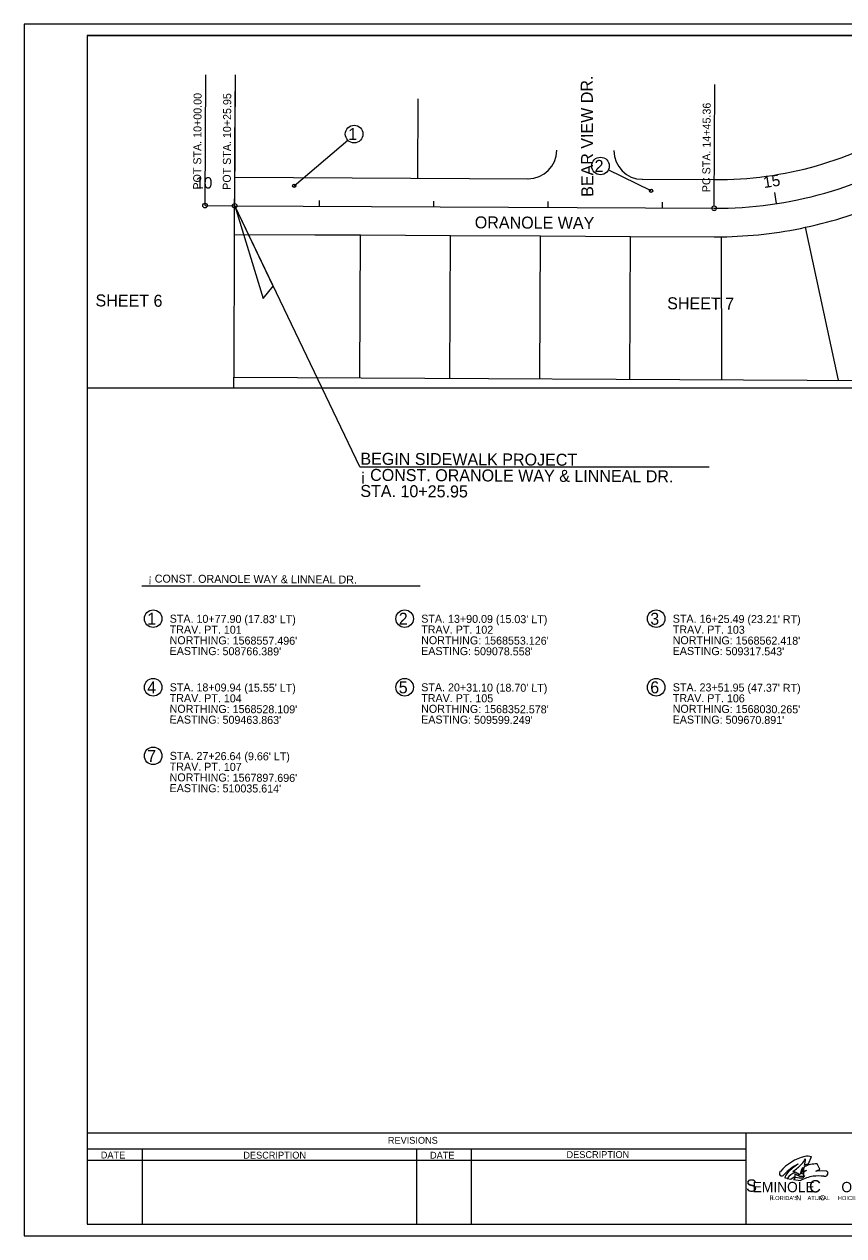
# Model space of a CAD drawing. Extents: x 508530 to 510180, y 1567639 to 1568699.
# Drawn here: x 508530 to 509247, y 1567639 to 1568699 of the extents above; entities that cross this region are included whole.
import ezdxf

# ---------------------------------------------------------------- set-up
doc = ezdxf.new("R2010")
doc.units = 0
for name, color, linetype in [('AdhocPoint_dp', 7, 'Continuous'), ('CLConst_dp', 7, 'Continuous'), ('CurveDataLabel_dp', 7, 'Continuous'), ('LeaderLine_dp', 7, 'Continuous'), ('Logo_dp', 7, 'Continuous'), ('NonPlottingEle_dp', 7, 'Continuous'), ('PlotBorder_dp', 7, 'Continuous'), ('RWLine_ep', 7, 'Continuous'), ('ScratchEle_dp', 7, 'Continuous'), ('SheetBorder_dp', 7, 'Continuous'), ('SheetLines_dp', 7, 'Continuous'), ('StationTicL_dp', 7, 'Continuous'), ('StationTicS_dp', 7, 'Continuous'), ('SubDivLine', 7, 'Continuous'), ('TextBLStation', 7, 'Continuous'), ('TextMisc', 7, 'Continuous')]:
    doc.layers.add(name, color=color, linetype=linetype)

msp = doc.modelspace()

# ---------------------------------------------------------------- linework, layer by layer
at = {"layer": 'AdhocPoint_dp'}
msp.add_line((508530.3, 1567638.8), (508530.3, 1567638.8), dxfattribs=at)
at = {"layer": 'CLConst_dp'}
for p, q in [((508688.4, 1568540.1), (508714.3, 1568539.9)), ((508714.3, 1568539.9), (509133.7, 1568537.8))]:
    msp.add_line(p, q, dxfattribs=at)
msp.add_arc((509135.5, 1568885.1), 347.3, 269.7131, 302.0065, dxfattribs=at)
at = {"layer": 'CurveDataLabel_dp'}
for p, q in [((508688.4, 1568542.1), (508689, 1568654.5)), ((508714.4, 1568541.9), (508714.9, 1568654.5)), ((509133.8, 1568539.8), (509134.3, 1568646.1))]:
    msp.add_line(p, q, dxfattribs=at)
for centre in [(508688.4, 1568540.1), (508714.3, 1568539.9), (509133.7, 1568537.8)]:
    msp.add_circle(centre, 2, dxfattribs=at)
at = {"layer": 'LeaderLine_dp'}
for p, q in [((508714.4, 1568539.9), (508739.3, 1568458.7)), ((508748.1, 1568469.6), (508714.4, 1568539.9)), ((508739.3, 1568458.7), (508748.1, 1568469.6))]:
    msp.add_line(p, q, dxfattribs=at)
at = {"layer": 'Logo_dp'}
for p, q in [((509216.3, 1567701.6), (509218.9, 1567708)), ((509226, 1567697.1), (509223.7, 1567701.7)), ((509197.5, 1567689), (509200.9, 1567688.4)), ((509200.9, 1567688.4), (509204.6, 1567690.8)), ((509203.2, 1567687.9), (509209.2, 1567687.1)), ((509204.6, 1567690.8), (509204.6, 1567692.3)), ((509206.3, 1567691.9), (509207.7, 1567692.8)), ((509212.7, 1567691.6), (509211.4, 1567689.6)), ((509231.6, 1567695.3), (509222.8, 1567695.5))]:
    msp.add_line(p, q, dxfattribs=at)
for points in [[(509212.9, 1567708.1), (509212.9, 1567708.1)], [(509198.1, 1567694.1), (509198.1, 1567694.1)]]:
    msp.add_lwpolyline(points, dxfattribs=at)
for centre, radius, start, end in [((509215.7, 1567696), 12.4, 75.3253, 102.9903), ((509221.9, 1567669.4), 39.7, 102.9903, 139.6059), ((509222.4, 1567668.5), 36.3, 114.9659, 139.5324), ((509232.3, 1567661.7), 47.1, 122.4911, 136.5671), ((509173.1, 1567737.9), 52, 304.6341, 315.4846), ((509226, 1567689.7), 17.3, 149.8559, 166.6084), ((509197.6, 1567713.8), 17.6, 315.4846, 334.5843), ((509221.2, 1567695.6), 10.4, 164.7271, 186.2913), ((509243.2, 1567692.9), 31.5, 168.5397, 176.4368), ((509223.2, 1567677.4), 24.3, 88.8097, 116.3253), ((509191.2, 1567706.8), 22.4, 343.2724, 358.4983), ((509220.3, 1567683.7), 18.4, 102.6743, 114.927), ((509193.9, 1567693.2), 3.05, 139.6059, 196.4516), ((509192.4, 1567692.7), 1.5, 196.4516, 259.2243), ((509192.7, 1567694), 2.81, 259.2243, 316.3038), ((509206.5, 1567686.1), 11.6, 136.5671, 163.5792), ((509187.6, 1567642.8), 47.2, 77.906, 80.5112), ((509215.4, 1567673.2), 23.8, 117.2749, 138.5612), ((509215.4, 1567673.2), 23.8, 117.2749, 138.5612), ((509200.1, 1567685.6), 9.82, 63.4009, 74.6531), ((509230.5, 1567666), 35, 136.6419, 141.2542), ((509203.1, 1567692), 1.52, 9.3089, 39.4038), ((509203.6, 1567690.2), 2.88, 52.8844, 76.2699), ((509189.3, 1567660.2), 37.4, 60.5981, 66.1485), ((509209.7, 1567709.7), 20.2, 256.604, 274.8219), ((509208.3, 1567696.3), 4.82, 231.8585, 245.4301), ((509244.2, 1567637.4), 65.6, 120.5054, 124.3665), ((509209.9, 1567696.9), 6.03, 242.5498, 297.6527), ((509224.5, 1567665.1), 32.4, 115.0847, 118.1751), ((509227.4, 1567652.4), 39.2, 100.5294, 117.6775), ((509214.7, 1567694.5), 3.85, 187.6078, 223.6575), ((509243.2, 1567692.9), 31.5, 177.2074, 179.7242), ((509216, 1567692.9), 4.27, 177.7479, 195.3391), ((509224.5, 1567665.1), 32.4, 108.2919, 113.1245), ((509244.2, 1567637.4), 65.6, 117.0216, 119.5789), ((509225, 1567638.5), 52.6, 84.8254, 95.1746), ((509219.2, 1567707.1), 12.2, 286.9862, 304.2368), ((509230.2, 1567694.7), 3.83, 262.9671, 309.9257), ((509231.7, 1567693.7), 1.61, 0.9885, 92.5741), ((509230.6, 1567693.5), 2.68, 319.3898, 5.6197)]:
    msp.add_arc(centre, radius, start, end, dxfattribs=at)
at = {"layer": 'NonPlottingEle_dp'}
msp.add_lwpolyline([(508585.3, 1568380.7), (509305.4, 1568380.7), (509301.4, 1567862), (509792.2, 1567850.3), (509790, 1567728.8), (510125.3, 1567728.8), (510125.3, 1568060.8), (510050.1, 1568061.2), (510050.5, 1568459.6), (509800.8, 1568459.6), (509800.8, 1568688.8), (508585.3, 1568688.8)], close=True, dxfattribs=at)
at = {"layer": 'PlotBorder_dp'}
msp.add_lwpolyline([(508530.3, 1567638.8), (510180.3, 1567638.8), (510180.3, 1568698.8), (508530.3, 1568698.8)], close=True, dxfattribs=at)
at = {"layer": 'RWLine_ep'}
for p, q in [((508714.5, 1568564.9), (508970.9, 1568563.6)), ((509070.9, 1568563.1), (509133.9, 1568562.8)), ((508714.3, 1568514.9), (508784.3, 1568514.6)), ((508784.3, 1568514.6), (508824.3, 1568514.4)), ((508824.3, 1568514.4), (508903, 1568514)), ((508903, 1568514), (508981.8, 1568513.6)), ((508981.8, 1568513.6), (509060.5, 1568513.2)), ((509060.5, 1568513.2), (509133.6, 1568512.8))]:
    msp.add_line(p, q, dxfattribs=at)
for centre, radius, start, end in [((509135.5, 1568885.1), 322.3, 269.7131, 301.9158), ((508971, 1568588.6), 25, 269.7131, 359.7131), ((509071, 1568588.1), 25, 179.7131, 269.7131), ((509135.5, 1568885.1), 372.3, 282.1234, 293.6661), ((509135.5, 1568885.1), 372.3, 270.6969, 282.1234), ((509135.5, 1568885.1), 372.3, 269.7131, 270.6969)]:
    msp.add_arc(centre, radius, start, end, dxfattribs=at)
at = {"layer": 'SheetBorder_dp'}
for p, q in [((508585.3, 1568688.8), (508585.3, 1567648.8)), ((508585.3, 1568688.8), (510125.3, 1568688.8)), ((508585.3, 1567728.8), (510125.3, 1567728.8)), ((508585.3, 1567648.8), (510125.3, 1567648.8))]:
    msp.add_line(p, q, dxfattribs=at)
at = {"layer": 'SheetLines_dp'}
for p, q in [((509161.3, 1567728.8), (509161.3, 1567648.8)), ((508585.3, 1567714.8), (509161.3, 1567714.8)), ((508633.3, 1567714.8), (508633.3, 1567648.8)), ((508873.3, 1567714.8), (508873.3, 1567648.8)), ((508921.3, 1567714.8), (508921.3, 1567648.8)), ((508585.3, 1567704.8), (509161.3, 1567704.8))]:
    msp.add_line(p, q, dxfattribs=at)
at = {"layer": 'StationTicL_dp'}
for p, q in [((508688.4, 1568540.1), (508688.4, 1568550.1)), ((509188.2, 1568541.8), (509186.7, 1568551.7))]:
    msp.add_line(p, q, dxfattribs=at)
at = {"layer": 'StationTicS_dp'}
for p, q in [((508788.4, 1568539.6), (508788.4, 1568544.6)), ((508888.4, 1568539.1), (508888.4, 1568544.1)), ((508988.4, 1568538.6), (508988.4, 1568543.6)), ((509088.4, 1568538.1), (509088.4, 1568543.1))]:
    msp.add_line(p, q, dxfattribs=at)
at = {"layer": 'SubDivLine'}
for p, q in [((508714.3, 1568514.9), (508714.8, 1568639.9)), ((508874.5, 1568564.1), (508874.8, 1568633.6)), ((508713.8, 1568389.9), (508714.3, 1568514.9)), ((508823.8, 1568389.4), (508824.3, 1568514.4)), ((508902.5, 1568389), (508903, 1568514)), ((509242.4, 1568387.3), (509213.7, 1568521.1)), ((508981.3, 1568388.6), (508981.8, 1568513.6)), ((509060, 1568388.2), (509060.5, 1568513.2)), ((509140.3, 1568387.8), (509140, 1568512.8)), ((508713.7, 1568389.9), (509333.6, 1568386.8)), ((508713.7, 1568380.7), (508713.7, 1568389.9))]:
    msp.add_line(p, q, dxfattribs=at)
at = {"layer": 'TextMisc'}
for p, q in [((508766.4, 1568557.5), (508813.4, 1568597.3)), ((509078.6, 1568553.1), (509041.1, 1568571.3)), ((508823.9, 1568311.5), (508714.4, 1568539.9)), ((508823.9, 1568311.5), (509129.4, 1568311.5)), ((508633.1, 1568207.3), (508876.5, 1568207.3))]:
    msp.add_line(p, q, dxfattribs=at)
for centre, radius in [((508818.8, 1568602.7), 7.69), ((509034.3, 1568574.8), 7.69), ((508766.4, 1568557.5), 1.44), ((509078.6, 1568553.1), 1.44), ((508643, 1568178.7), 7.69), ((508863, 1568178.7), 7.69), ((509083, 1568178.7), 7.69), ((508643, 1568118.7), 7.69), ((508863, 1568118.7), 7.69), ((509083, 1568118.7), 7.69), ((508643, 1568058.7), 7.69)]:
    msp.add_circle(centre, radius, dxfattribs=at)

# ---------------------------------------------------------------- texts
at = {"layer": 'CurveDataLabel_dp'}
for s, p in [('POT STA. 10+00.00', (508685, 1568554.1)), ('POT STA. 10+25.95', (508710.9, 1568553.9)), ('PC STA. 14+45.36', (509130.3, 1568551.8))]:
    msp.add_text(s, height=7, rotation=89.7131, dxfattribs=at).set_placement(p)
at = {"layer": 'Logo_dp'}
for s, height, p in [('S', 10.8, (509161.5, 1567677.3)), ('C', 10.8, (509216.7, 1567676.7)), ('EMINOLE       OUNTY', 9, (509167.4, 1567676.9)), ('F', 4.5, (509181.9, 1567669.8)), ("LORIDA'S      ATURAL     HOICE", 3.6, (509184.3, 1567670)), ('N', 4.5, (509205.3, 1567669.8)), ('C', 4.5, (509226.2, 1567669.8))]:
    msp.add_text(s, height=height, dxfattribs=at).set_placement(p)
at = {"layer": 'ScratchEle_dp'}
for s, p in [('Sheet: 1', (508585.3, 1567729)), ('Angle:  90.0153', (508585.3, 1567728.6)), ('Align: CH269', (508585.3, 1567728.2))]:
    msp.add_text(s, height=0.295, dxfattribs=at).set_placement(p)
at = {"layer": 'TextBLStation'}
for s, rotation, p in [('15', 8.7278, (509177.4, 1568555.4)), ('10', 359.7131, (508679.9, 1568555.1))]:
    msp.add_text(s, height=10, rotation=rotation, dxfattribs=at).set_placement(p)
at = {"layer": 'TextMisc'}
for s, height, rotation, p in [('BEAR VIEW DR.', 10.5, 90.2729, (509028, 1568547.8)), ('1', 10.5, 359.7131, (508813.6, 1568597.5)), ('2', 10.5, 359.7131, (509029.1, 1568569.6)), ('ORANOLE WAY', 10.5, 359.7131, (508924.3, 1568520.2)), ('SHEET 6', 10.5, 359.7131, (508592.6, 1568451.9)), ('SHEET 7', 10.5, 359.7131, (509092.6, 1568449.4)), ('BEGIN SIDEWALK PROJECT', 10.5, 359.7131, (508824.3, 1568313.4)), ('¡ CONST. ORANOLE WAY & LINNEAL DR.', 10.5, 359.7131, (508824.2, 1568299.3)), ('STA. 10+25.95', 10.5, 359.7131, (508824.2, 1568285.2)), ('¡ CONST. ORANOLE WAY & LINNEAL DR.', 7, 359.7131, (508638.7, 1568210.3)), ('1', 10.5, 359.7131, (508637.8, 1568173.4)), ("STA. 10+77.90 (17.83' LT)", 7, 359.7131, (508657.5, 1568175.2)), ('2', 10.5, 359.7131, (508857.8, 1568173.4)), ("STA. 13+90.09 (15.03' LT)", 7, 359.7131, (508877.5, 1568175.2)), ('3', 10.5, 359.7131, (509077.8, 1568173.4)), ("STA. 16+25.49 (23.21' RT)", 7, 359.7131, (509097.5, 1568175.2)), ('TRAV. PT. 101', 7, 359.7131, (508657.5, 1568165.8)), ('TRAV. PT. 102', 7, 359.7131, (508877.5, 1568165.8)), ('TRAV. PT. 103', 7, 359.7131, (509097.5, 1568165.8)), ("NORTHING: 1568557.496'", 7, 359.7131, (508657.4, 1568156.4)), ("EASTING: 508766.389'", 7, 359.7131, (508657.4, 1568147)), ("NORTHING: 1568553.126'", 7, 359.7131, (508877.4, 1568156.4)), ("EASTING: 509078.558'", 7, 359.7131, (508877.4, 1568147)), ("NORTHING: 1568562.418'", 7, 359.7131, (509097.4, 1568156.4)), ("EASTING: 509317.543'", 7, 359.7131, (509097.4, 1568147)), ('4', 10.5, 359.7131, (508637.8, 1568113.4)), ("STA. 18+09.94 (15.55' LT)", 7, 359.7131, (508657.5, 1568115.2)), ('5', 10.5, 359.7131, (508857.8, 1568113.4)), ("STA. 20+31.10 (18.70' LT)", 7, 359.7131, (508877.5, 1568115.2)), ('6', 10.5, 359.7131, (509077.8, 1568113.4)), ("STA. 23+51.95 (47.37' RT)", 7, 359.7131, (509097.5, 1568115.2)), ('TRAV. PT. 104', 7, 359.7131, (508657.5, 1568105.8)), ('TRAV. PT. 105', 7, 359.7131, (508877.5, 1568105.8)), ('TRAV. PT. 106', 7, 359.7131, (509097.5, 1568105.8)), ("NORTHING: 1568528.109'", 7, 359.7131, (508657.4, 1568096.4)), ("NORTHING: 1568352.578'", 7, 359.7131, (508877.4, 1568096.4)), ("NORTHING: 1568030.265'", 7, 359.7131, (509097.4, 1568096.4)), ("EASTING: 509463.863'", 7, 359.7131, (508657.4, 1568087)), ("EASTING: 509599.249'", 7, 359.7131, (508877.4, 1568087)), ("EASTING: 509670.891'", 7, 359.7131, (509097.4, 1568087)), ('7', 10.5, 359.7131, (508637.8, 1568053.4)), ("STA. 27+26.64 (9.66' LT)", 7, 359.7131, (508657.5, 1568055.2)), ('TRAV. PT. 107', 7, 359.7131, (508657.5, 1568045.8)), ("NORTHING: 1567897.696'", 7, 359.7131, (508657.4, 1568036.4)), ("EASTING: 510035.614'", 7, 359.7131, (508657.4, 1568027)), ('REVISIONS', 6, 360, (508848.3, 1567719.3)), ('DATE', 6, 359.8693, (508597.2, 1567706.4)), ('DESCRIPTION', 6, 0.0498, (508721.9, 1567706.3)), ('DATE', 6, 359.8693, (508885.2, 1567706.3)), ('DESCRIPTION', 6, 0.0498, (509004.6, 1567706.8))]:
    msp.add_text(s, height=height, rotation=rotation, dxfattribs=at).set_placement(p)

doc.saveas('drawing.dxf')
